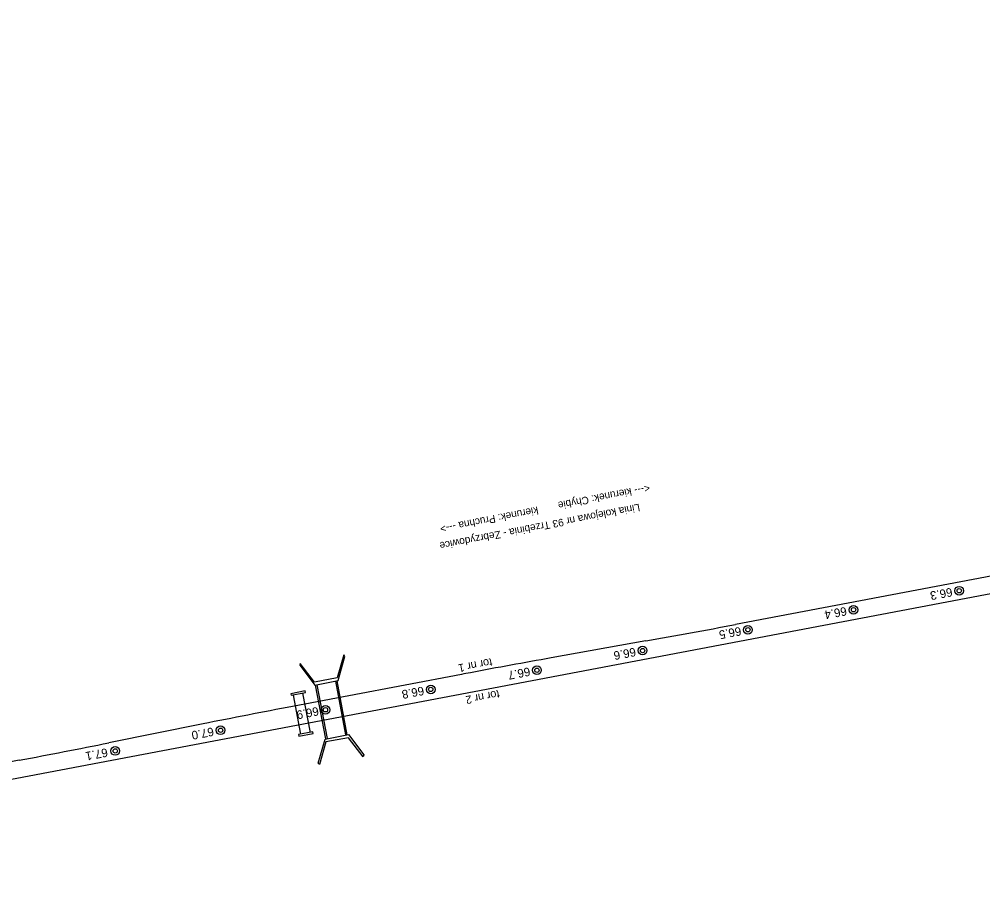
# Model space of a CAD drawing. Extents: x 6541740 to 6556805, y 5525233 to 5530361.
# Drawn here: x 6555803.5 to 6556027.8, y 5525870.4 to 5526073.7 of the extents above; entities that cross this region are included whole.
import ezdxf

# ---------------------------------------------------------------- set-up
doc = ezdxf.new("R2010")
doc.units = 0
for name, color, linetype in [('Default', 7, 'Continuous'), ('TOR_PS_OPIS_T-numeracja torow i rozjazdow', 7, 'Continuous'), ('TOR_SCH-hektometry', 7, 'Continuous'), ('TOR_SCH-obiekty istniejace', 7, 'Continuous'), ('TOR_SCH-obiekty projektowane', 7, 'Continuous'), ('TOR_SCH-opisy dodatkowe', 7, 'Continuous'), ('TOR_SCH-tory projektowane', 7, 'Continuous')]:
    doc.layers.add(name, color=color, linetype=linetype)

# ---------------------------------------------------------------- blocks, each defined once
blk = doc.blocks.new('4010_1')
at = {"layer": 'Default'}
for radius in [0.75, 0.375]:
    blk.add_circle((0, 0), radius, dxfattribs=at)

msp = doc.modelspace()

# ---------------------------------------------------------------- linework, layer by layer
at = {"layer": 'TOR_SCH-obiekty istniejace'}
for p, q in [((6555870.07, 5525917.4), (6555866.71, 5525916.76)), ((6555866.71, 5525916.76), (6555866.78, 5525916.39)), ((6555866.78, 5525916.39), (6555870.13, 5525917.02)), ((6555869.08, 5525907.35), (6555867.31, 5525916.43)), ((6555869.45, 5525916.89), (6555871.24, 5525907.76)), ((6555870.13, 5525917.02), (6555870.07, 5525917.4)), ((6555871.86, 5525907.88), (6555868.5, 5525907.24)), ((6555868.5, 5525907.24), (6555868.57, 5525906.87)), ((6555868.57, 5525906.87), (6555871.93, 5525907.5)), ((6555871.93, 5525907.5), (6555871.86, 5525907.88))]:
    msp.add_line(p, q, dxfattribs=at)
at = {"layer": 'TOR_SCH-obiekty projektowane'}
for points in [[(6555868.92, 5525923.83), (6555868.79, 5525923.38), (6555872.3, 5525918.78), (6555877.72, 5525919.8), (6555879.32, 5525925.45), (6555879.03, 5525925.83), (6555877.51, 5525920.48), (6555872.24, 5525919.48), (6555868.92, 5525923.83)], [(6555874.87, 5525906.28), (6555872.5, 5525918.78)], [(6555875.23, 5525906.35), (6555872.86, 5525918.85)], [(6555879.53, 5525907.16), (6555877.16, 5525919.66)], [(6555879.85, 5525907.22), (6555877.48, 5525919.72)], [(6555874.69, 5525906.21), (6555880.11, 5525907.23), (6555883.68, 5525902.55), (6555883.55, 5525902.09), (6555880.17, 5525906.53), (6555874.9, 5525905.53), (6555873.4, 5525900.25), (6555873.12, 5525900.63), (6555874.69, 5525906.21)]]:
    msp.add_lwpolyline(points, dxfattribs=at)
at = {"layer": 'TOR_SCH-tory projektowane'}
for p, q in [((6556735.03, 5526073.73), (6555909.41, 5525917.23)), ((6556139.45, 5525964.96), (6555970.25, 5525932.89)), ((6555949.35, 5525929.04), (6555927.34, 5525925.1)), ((6555906.44, 5525921.25), (6555867.14, 5525913.8)), ((6555909.41, 5525917.23), (6555662.57, 5525870.44)), ((6555846.28, 5525909.73), (6555824.35, 5525905.34)), ((6555846.28, 5525909.73), (6555824.35, 5525905.34)), ((6555803.5, 5525901.28), (6555661.88, 5525874.43))]:
    msp.add_line(p, q, dxfattribs=at)
for centre, start_param, end_param in [((6549833.75, 5558306.42), 3.139013, 3.141593), ((6562042.93, 5493547.71), 6.280606, 6.282925), ((6562042.93, 5493547.71), 6.282925, 6.283185), ((6562003.63, 5493540.26), 6.283185, 6.285765), ((6549667, 5558274.81), 3.141593, 3.144172)]:
    msp.add_ellipse(centre, major_axis=(-6136.5, 32373.54), ratio=0.25, start_param=start_param, end_param=end_param, dxfattribs=at)

# ---------------------------------------------------------------- block references
at = {"layer": 'TOR_SCH-hektometry', "xscale": 1.345963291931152, "yscale": 1.345963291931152}
for p in [(6556022.32, 5525940.74), (6555997.72, 5525936.3), (6555973.15, 5525931.64), (6555948.62, 5525926.8), (6555924.03, 5525922.23), (6555899.3, 5525917.76), (6555874.79, 5525913.01), (6555850.36, 5525908.25), (6555825.83, 5525903.43)]:
    msp.add_blockref('4010_1', p, dxfattribs=at)

# ---------------------------------------------------------------- texts
at = {"layer": 'TOR_PS_OPIS_T-numeracja torow i rozjazdow'}
for s, p in [('tor nr 1', (6555913.4, 5525925.04)), ('tor nr 2', (6555915.1, 5525917.63))]:
    msp.add_text(s, height=1.875, rotation=190.7101, dxfattribs=at).set_placement(p)
at = {"layer": 'TOR_SCH-hektometry'}
for s, p in [('66.3', (6556020.54, 5525941.45)), ('66.4', (6555995.94, 5525937)), ('66.5', (6555971.38, 5525932.35)), ('66.6', (6555946.85, 5525927.51)), ('66.7', (6555922.25, 5525922.93)), ('66.8', (6555897.53, 5525918.47)), ('66.9', (6555873.01, 5525913.72)), ('67.0', (6555848.58, 5525908.96)), ('67.1', (6555823.89, 5525904.11))]:
    msp.add_text(s, height=2, rotation=190.7691, dxfattribs=at).set_placement(p)
at = {"layer": 'TOR_SCH-opisy dodatkowe'}
for s, height, rotation, p in [('<--- kierunek: Chybie', 1.75, 191.0012, (6555950.16, 5525965.52)), ('Linia kolejowa nr 93 Trzebinia - Zebrzydowice', 1.7499, 190.987, (6555947.82, 5525961.01)), ('kierunek: Pruchna --->', 1.75, 191.0012, (6555924.15, 5525960.32))]:
    msp.add_text(s, height=height, rotation=rotation, dxfattribs=at).set_placement(p)

doc.saveas('drawing.dxf')
